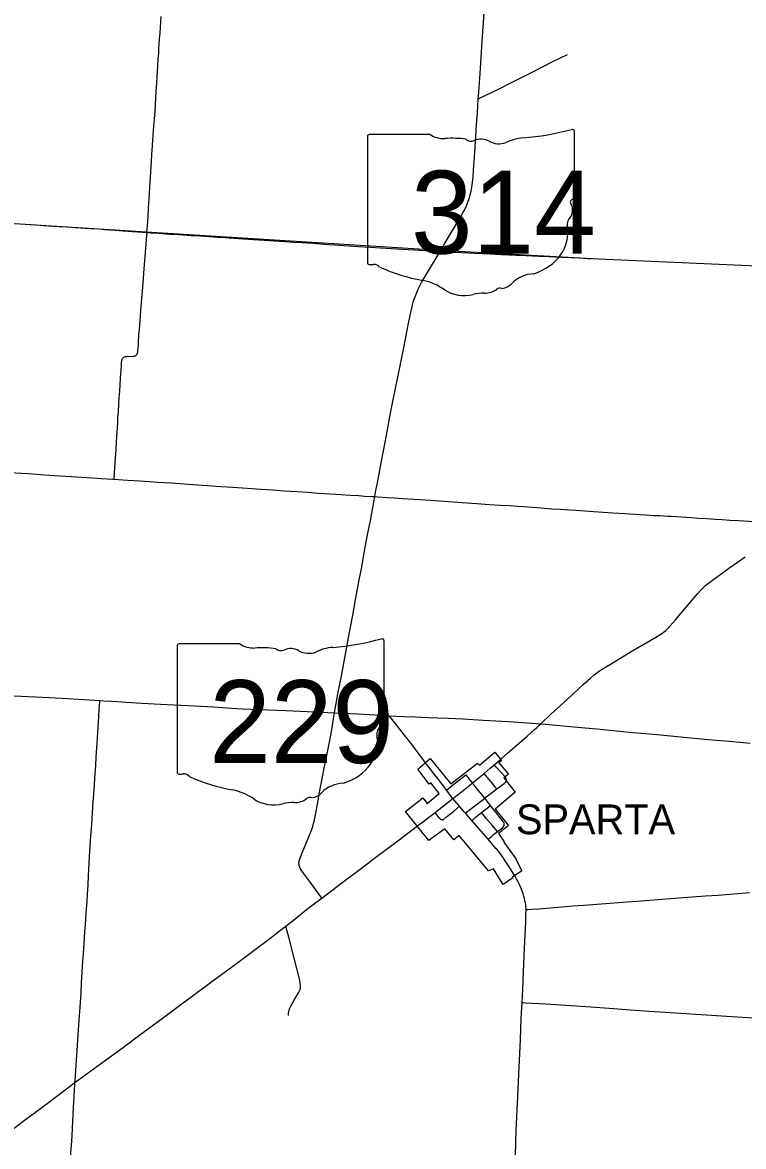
# Model space of a CAD drawing. Extents: x 1815539 to 1947826, y 273303 to 993194.
# Drawn here: x 1905397 to 1917520, y 866502 to 885394 of the extents above; entities that cross this region are included whole.
import ezdxf

# ---------------------------------------------------------------- set-up
doc = ezdxf.new("R2010")
doc.units = 0
for name, color, linetype in [('GM_X_City_Street', 7, 'Continuous'), ('GM_X_Corporation', 7, 'Continuous'), ('GM_X_Corporation_Text', 7, 'Continuous'), ('GM_X_County_Road', 7, 'Continuous'), ('GM_X_State_Route', 7, 'Continuous'), ('GM_X_Township', 7, 'Continuous'), ('GM_X_Township_Road', 7, 'Continuous'), ('SC_Shading3', 7, 'Continuous')]:
    doc.layers.add(name, color=color, linetype=linetype)

msp = doc.modelspace()

# ---------------------------------------------------------------- linework, layer by layer
at = {"layer": 'GM_X_City_Street'}
for points in [[(1913534, 872652), (1913534, 872655), (1913534, 872657), (1913534, 872659), (1913534, 872660), (1913534, 872662), (1913534, 872665), (1913533, 872671), (1913532, 872677), (1913530, 872681), (1913528, 872687), (1913526, 872690), (1913525, 872693), (1913522, 872699), (1913516, 872706), (1913510, 872715), (1913451, 872780), (1913356, 872886), (1913328, 872917)], [(1912525, 872493), (1912622, 872568), (1912846, 872742), (1912847, 872743), (1912848, 872744), (1912849, 872744), (1912850, 872744), (1912851, 872745), (1912852, 872745), (1912855, 872745)], [(1912960, 872610), (1912950, 872624), (1912867, 872732), (1912861, 872740), (1912861, 872741), (1912860, 872741), (1912858, 872743), (1912858, 872743), (1912857, 872744), (1912855, 872745)], [(1913168, 872356), (1913142, 872389), (1913010, 872554), (1912997, 872571), (1912988, 872581), (1912981, 872589), (1912972, 872599), (1912960, 872610)], [(1913372, 872513), (1913357, 872532), (1913276, 872632), (1913183, 872744), (1913158, 872773)], [(1913372, 872513), (1913431, 872556), (1913496, 872605), (1913513, 872620), (1913517, 872624), (1913522, 872629), (1913525, 872634), (1913529, 872641), (1913530, 872644), (1913531, 872646), (1913532, 872648), (1913533, 872651), (1913534, 872652)], [(1913168, 872356), (1913173, 872360), (1913275, 872438), (1913352, 872498), (1913372, 872513)], [(1912843, 872105), (1912864, 872121), (1913045, 872260), (1913168, 872356)], [(1913114, 872113), (1913238, 872213), (1913263, 872235)], [(1913263, 872235), (1913168, 872356)], [(1913494, 871894), (1913496, 871899), (1913497, 871905), (1913497, 871911), (1913497, 871918), (1913496, 871928), (1913494, 871935), (1913492, 871941), (1913489, 871947), (1913484, 871956), (1913474, 871969), (1913451, 872000), (1913424, 872034), (1913353, 872122), (1913328, 872155), (1913283, 872211), (1913263, 872235)], [(1912453, 871991), (1912449, 871991), (1912446, 871992), (1912443, 871993), (1912441, 871994), (1912438, 871995), (1912436, 871996), (1912434, 871997), (1912430, 872000), (1912426, 872003), (1912421, 872009), (1912417, 872012), (1912413, 872017), (1912388, 872046), (1912357, 872085), (1912333, 872117)], [(1912453, 871991), (1912456, 871991), (1912459, 871991), (1912462, 871992), (1912465, 871992), (1912466, 871992), (1912467, 871993), (1912469, 871994), (1912470, 871995), (1912471, 871996), (1912473, 871997), (1912526, 872041), (1912647, 872140), (1912742, 872221)], [(1912952, 871981), (1912972, 871998), (1913010, 872029), (1913114, 872113)], [(1913384, 871796), (1913287, 871910), (1913199, 872009), (1913160, 872057), (1913114, 872113)], [(1913384, 871796), (1913466, 871859), (1913486, 871878), (1913491, 871885), (1913492, 871889), (1913494, 871894)], [(1913225, 871666), (1913252, 871688), (1913289, 871719), (1913313, 871740), (1913340, 871762), (1913384, 871796)]]:
    msp.add_lwpolyline(points, dxfattribs=at)
at = {"layer": 'GM_X_Corporation'}
msp.add_lwpolyline([(1913233, 871137), (1912739, 871727), (1912650, 871656), (1912497, 871840), (1912228, 871646), (1911837, 872131), (1912128, 872361), (1912202, 872267), (1912400, 872433), (1912262, 872613), (1912235, 872592), (1912045, 872846), (1912253, 873024), (1912601, 872595), (1913046, 872947), (1913082, 872913), (1913338, 873127), (1913450, 872989), (1913407, 872950), (1913568, 872762), (1913491, 872701), (1913680, 872455), (1913345, 872174), (1913569, 871895), (1913400, 871760), (1913496, 871622), (1913488, 871616), (1913679, 871355), (1913791, 871135), (1913633, 871028), (1913642, 871016), (1913476, 870904), (1913318, 871168)], close=True, dxfattribs=at)
at = {"layer": 'GM_X_County_Road'}
for points in [[(1905171, 882022), (1905449, 882003), (1905629, 881991), (1905826, 881978), (1906016, 881966), (1906157, 881957), (1906291, 881947), (1906537, 881932), (1906678, 881923), (1906775, 881914), (1906954, 881901), (1907085, 881891), (1907249, 881879), (1907413, 881867), (1907489, 881862)], [(1907489, 881862), (1907560, 881857), (1907691, 881850), (1907871, 881838), (1907953, 881833), (1908231, 881815), (1908378, 881805), (1908542, 881794), (1908673, 881785), (1908804, 881777), (1908869, 881773), (1909033, 881763), (1909278, 881747), (1909458, 881736), (1909624, 881726), (1909802, 881714), (1909966, 881703), (1910097, 881694), (1910277, 881682), (1910474, 881668), (1910637, 881657), (1911047, 881631), (1911243, 881618), (1911505, 881601), (1911783, 881585), (1911980, 881574), (1912259, 881558), (1912420, 881547)], [(1914112, 873607), (1914282, 873766), (1914500, 873965), (1914632, 874088), (1914825, 874266), (1914947, 874375), (1915010, 874428), (1915061, 874468), (1915101, 874496), (1915170, 874540), (1915366, 874660), (1915633, 874821), (1916057, 875070), (1916127, 875113), (1916168, 875141), (1916207, 875171), (1916243, 875205), (1916288, 875253), (1916374, 875353), (1916619, 875640), (1916747, 875789), (1916801, 875850), (1916846, 875897), (1916882, 875930), (1916932, 875972), (1916997, 876022), (1917291, 876232), (1917545, 876411)], [(1906279, 867576), (1906289, 867687), (1906301, 867867), (1906324, 868201), (1906336, 868382), (1906351, 868620), (1906357, 868701), (1906361, 868767), (1906372, 868930), (1906382, 869077), (1906392, 869258), (1906397, 869339), (1906403, 869437), (1906409, 869536), (1906424, 869748), (1906435, 869912), (1906448, 870108), (1906452, 870174), (1906461, 870304), (1906470, 870435), (1906482, 870615), (1906491, 870746), (1906500, 870893), (1906508, 871057), (1906514, 871155), (1906524, 871368), (1906542, 871647), (1906561, 871908), (1906582, 872219), (1906606, 872579), (1906614, 872694), (1906628, 872906), (1906638, 873054), (1906653, 873283), (1906665, 873463), (1906679, 873725), (1906688, 873859), (1906695, 873970), (1906696, 873998)], [(1906139, 865355), (1906148, 865479), (1906161, 865659), (1906173, 865815), (1906185, 866019), (1906199, 866231), (1906205, 866329), (1906219, 866526), (1906230, 866675), (1906238, 866822), (1906244, 866918), (1906256, 867164), (1906266, 867327), (1906272, 867458), (1906276, 867540), (1906279, 867576)]]:
    msp.add_lwpolyline(points, dxfattribs=at)
at = {"layer": 'GM_X_State_Route'}
for points in [[(1910643, 873793), (1910707, 874140), (1910753, 874381), (1910856, 874930), (1910907, 875204), (1910949, 875430), (1910998, 875688), (1911060, 876027), (1911100, 876237), (1911144, 876479), (1911200, 876785), (1911246, 877026), (1911292, 877268), (1911321, 877425), (1911339, 877526), (1911369, 877687), (1911428, 877994), (1911506, 878396), (1911563, 878703), (1911604, 878919), (1911626, 879026), (1911752, 879649), (1911812, 879955), (1911861, 880196), (1911884, 880313), (1911926, 880517), (1911942, 880591), (1911954, 880646), (1911968, 880694), (1911983, 880745), (1911997, 880785), (1912014, 880829), (1912031, 880868), (1912045, 880898), (1912074, 880959), (1912108, 881023), (1912207, 881194), (1912420, 881547), (1912494, 881672), (1912578, 881813), (1912645, 881926), (1912755, 882109), (1912803, 882194), (1912833, 882252), (1912861, 882312), (1912886, 882372), (1912907, 882434), (1912926, 882496), (1912940, 882560), (1912952, 882624), (1912963, 882705), (1912973, 882803), (1912982, 882918), (1912995, 883130), (1913018, 883474), (1913026, 883589), (1913037, 883752), (1913045, 883867), (1913053, 883997), (1913061, 884110), (1913069, 884225), (1913090, 884536), (1913107, 884798), (1913128, 885093), (1913147, 885387), (1913176, 885829)], [(1905259, 874074), (1905735, 874054), (1906062, 874039), (1906439, 874017), (1906696, 873998), (1906766, 873993), (1906995, 873980), (1907143, 873972), (1907404, 873956), (1907716, 873938), (1907945, 873925), (1908289, 873909), (1908616, 873889), (1908911, 873869), (1909091, 873858), (1909238, 873850), (1909533, 873839), (1909828, 873828), (1910419, 873804), (1910643, 873793)], [(1910643, 873793), (1911029, 873772), (1911523, 873744), (1911561, 873742)], [(1911561, 873742), (1911801, 873729), (1911998, 873721), (1912211, 873713), (1912555, 873700), (1912799, 873688), (1913141, 873670), (1913566, 873644), (1913959, 873618), (1914112, 873607)], [(1912172, 872953), (1912128, 873011), (1911930, 873273), (1911800, 873443), (1911660, 873625), (1911597, 873701), (1911561, 873742)], [(1913438, 873010), (1913558, 873116), (1913668, 873215), (1913880, 873400), (1913999, 873504), (1914042, 873542), (1914078, 873576), (1914112, 873607)], [(1914112, 873607), (1914188, 873602), (1914727, 873549), (1915054, 873520), (1915657, 873463), (1916065, 873425), (1916572, 873378), (1916930, 873345), (1917338, 873308), (1917632, 873282)], [(1913394, 872974), (1913438, 873010)], [(1912037, 871890), (1912059, 871906), (1912333, 872117), (1912369, 872145), (1912634, 872350), (1912779, 872464), (1912920, 872577), (1912960, 872610), (1913048, 872680), (1913158, 872773), (1913262, 872859), (1913328, 872917), (1913394, 872974)], [(1913370, 871497), (1913357, 871513), (1913225, 871666), (1912984, 871944), (1912952, 871981), (1912843, 872105), (1912823, 872127), (1912742, 872221), (1912634, 872350), (1912525, 872493), (1912491, 872539), (1912254, 872850), (1912172, 872953)], [(1905195, 866767), (1905433, 866942), (1905656, 867109), (1905788, 867207), (1906115, 867454), (1906279, 867576), (1906339, 867621), (1906525, 867756), (1906671, 867862), (1907094, 868173), (1907371, 868378), (1907767, 868670), (1907925, 868788), (1908084, 868904), (1908229, 869012), (1908560, 869258), (1908996, 869580), (1909598, 870031), (1909740, 870142), (1909822, 870205), (1909980, 870331), (1910174, 870483), (1910330, 870603), (1910428, 870676), (1910790, 870948), (1911118, 871196), (1911340, 871366), (1911708, 871642), (1912037, 871890)], [(1913672, 871054), (1913601, 871170), (1913513, 871303), (1913471, 871366), (1913415, 871442), (1913370, 871497)], [(1913685, 866348), (1913693, 866577), (1913699, 866773), (1913710, 867002), (1913725, 867346), (1913749, 867838), (1913769, 868296), (1913784, 868657), (1913796, 868921), (1913807, 869148), (1913827, 869574), (1913837, 869836), (1913858, 870277), (1913862, 870354), (1913862, 870407), (1913864, 870466), (1913864, 870483), (1913864, 870489), (1913863, 870507), (1913861, 870532), (1913857, 870560), (1913852, 870595), (1913845, 870631), (1913837, 870668), (1913828, 870704), (1913814, 870751), (1913788, 870829), (1913772, 870867), (1913755, 870904), (1913731, 870951), (1913710, 870992), (1913672, 871054)]]:
    msp.add_lwpolyline(points, dxfattribs=at)
at = {"layer": 'GM_X_Township'}
msp.add_lwpolyline([(1929313, 880637), (1926519, 880798), (1923978, 880945), (1923826, 880954), (1918127, 881283), (1915079, 881414), (1912418, 881561), (1907482, 881867), (1902065, 882212), (1902276, 885593), (1902366, 887154), (1902378, 887248), (1902624, 890798), (1902935, 895772), (1903241, 901246), (1903453, 905734), (1903500, 906547), (1903661, 909327)], dxfattribs=at)
at = {"layer": 'GM_X_Township_Road'}
for points in [[(1907489, 881862), (1907499, 881979), (1907508, 882126), (1907517, 882274), (1907533, 882519), (1907545, 882716), (1907554, 882880), (1907560, 882978), (1907564, 883060), (1907572, 883174), (1907577, 883245), (1907583, 883325), (1907590, 883423), (1907607, 883658), (1907616, 883766), (1907627, 883908), (1907641, 884120), (1907647, 884235), (1907657, 884382), (1907663, 884480), (1907673, 884660), (1907681, 884775), (1907687, 884873), (1907692, 884955), (1907703, 885118), (1907711, 885216), (1907718, 885314), (1907730, 885495)], [(1913061, 884110), (1913174, 884164), (1913389, 884270), (1913653, 884402), (1913800, 884476), (1913975, 884566), (1914151, 884656), (1914312, 884738), (1914444, 884801), (1914559, 884855)], [(1906935, 877716), (1906936, 877737), (1906944, 877818), (1906952, 877917), (1906962, 878064), (1906971, 878212), (1906979, 878343), (1906985, 878424), (1906998, 878670), (1907003, 878752), (1907010, 878850), (1907018, 878981), (1907025, 879096), (1907028, 879128), (1907033, 879210), (1907038, 879292), (1907047, 879428), (1907054, 879547), (1907060, 879632), (1907063, 879681), (1907067, 879713), (1907071, 879729), (1907078, 879744), (1907088, 879756), (1907100, 879766), (1907115, 879774), (1907131, 879778), (1907147, 879781), (1907164, 879783), (1907246, 879782), (1907263, 879783), (1907279, 879785), (1907293, 879791), (1907307, 879800), (1907319, 879812), (1907328, 879827), (1907337, 879854), (1907339, 879873), (1907343, 879929), (1907346, 879988), (1907348, 880051), (1907352, 880103), (1907355, 880132), (1907356, 880160), (1907362, 880225), (1907371, 880324), (1907374, 880373), (1907388, 880552), (1907389, 880569), (1907393, 880618), (1907411, 880814), (1907426, 881011), (1907445, 881256), (1907456, 881386), (1907477, 881665), (1907487, 881812), (1907488, 881845), (1907489, 881862)], [(1912420, 881547), (1912541, 881539), (1912639, 881533), (1912787, 881527), (1912983, 881518), (1913131, 881511), (1913262, 881505), (1913442, 881496), (1913704, 881485), (1913868, 881477), (1914081, 881468), (1914245, 881462), (1914458, 881452), (1914625, 881444), (1914753, 881438), (1914901, 881429), (1914963, 881427)], [(1904181, 877893), (1904201, 877892), (1904299, 877888), (1904430, 877881), (1904512, 877877), (1904659, 877867), (1904790, 877859), (1905003, 877844), (1905183, 877832), (1905379, 877820), (1905494, 877813), (1905854, 877787), (1906214, 877763), (1906574, 877738), (1906721, 877728), (1906918, 877717), (1906935, 877716)], [(1906935, 877716), (1907164, 877701), (1907376, 877688), (1907671, 877669), (1907900, 877654), (1908195, 877633), (1908342, 877624)], [(1908342, 877624), (1908506, 877614), (1908735, 877597), (1908931, 877584), (1909095, 877572), (1909259, 877562), (1909324, 877557), (1909504, 877543), (1909602, 877536), (1909798, 877523), (1910011, 877508), (1910190, 877497), (1910369, 877485), (1910755, 877460), (1910905, 877450), (1911049, 877442), (1911147, 877435), (1911290, 877427), (1911321, 877425)], [(1911321, 877425), (1911378, 877422), (1911527, 877410), (1911644, 877404), (1911780, 877395), (1912174, 877368), (1912559, 877340), (1912722, 877329), (1912792, 877324), (1913038, 877308), (1913175, 877299), (1913340, 877289), (1913433, 877283), (1913577, 877273), (1913725, 877263), (1913826, 877256), (1913977, 877245), (1914120, 877235), (1914292, 877222), (1914443, 877212), (1914508, 877208), (1914590, 877203), (1914705, 877195), (1914852, 877185), (1914999, 877175), (1915081, 877169), (1915162, 877165), (1915326, 877154), (1915522, 877142), (1915604, 877137), (1915702, 877132), (1915784, 877127), (1915882, 877119), (1916013, 877110), (1916112, 877105), (1916243, 877098), (1916308, 877094), (1916390, 877090), (1916553, 877080), (1916651, 877073), (1916766, 877065), (1916897, 877057), (1917044, 877048), (1917158, 877040), (1917289, 877030), (1917437, 877022), (1917699, 877009)], [(1910428, 870676), (1910417, 870691), (1910238, 870939), (1910121, 871096), (1910084, 871150), (1910067, 871178), (1910060, 871192), (1910054, 871207), (1910050, 871222), (1910047, 871237), (1910046, 871253), (1910046, 871269), (1910048, 871285), (1910051, 871301), (1910059, 871333), (1910069, 871364), (1910097, 871440), (1910142, 871546), (1910206, 871697), (1910256, 871819), (1910278, 871881), (1910292, 871929), (1910307, 871993), (1910330, 872106), (1910367, 872317), (1910387, 872430), (1910425, 872623), (1910466, 872833), (1910513, 873073), (1910535, 873188), (1910557, 873300), (1910590, 873478), (1910625, 873688), (1910643, 873793)], [(1913864, 870483), (1913901, 870486), (1913966, 870490), (1914081, 870499), (1914457, 870529), (1914654, 870545), (1914916, 870565), (1915129, 870583), (1915276, 870594), (1915555, 870616), (1915735, 870628), (1916144, 870660), (1916505, 870686), (1916882, 870713), (1917095, 870729), (1917357, 870750), (1917619, 870770)], [(1909868, 868703), (1909869, 868736), (1909873, 868768), (1909887, 868815), (1909915, 868874), (1909972, 868973), (1910038, 869087), (1910059, 869131), (1910063, 869140), (1910066, 869146), (1910067, 869152), (1910069, 869159), (1910070, 869164), (1910071, 869172), (1910072, 869181), (1910072, 869188), (1910071, 869194), (1910070, 869203), (1910069, 869215), (1910066, 869234), (1910063, 869255), (1910058, 869286), (1910047, 869341), (1909959, 869690), (1909885, 869976), (1909822, 870205)], [(1913796, 868921), (1913819, 868920), (1913856, 868918), (1914196, 868898), (1914441, 868881), (1914711, 868865), (1914950, 868848), (1915263, 868826), (1915622, 868800), (1915933, 868778), (1916555, 868736), (1916718, 868726), (1917848, 868654)]]:
    msp.add_lwpolyline(points, dxfattribs=at)
at = {"layer": 'SC_Shading3'}
for p, q in [((1911195, 883474), (1911195, 881360)), ((1912249, 883510), (1911230, 883510)), ((1914676, 882457), (1914676, 883562)), ((1914676, 882457), (1914676, 882457)), ((1907997, 874911), (1907997, 872798)), ((1909050, 874948), (1908031, 874948)), ((1911477, 873895), (1911477, 875000)), ((1911477, 873895), (1911477, 873895))]:
    msp.add_line(p, q, dxfattribs=at)
for centre, major_axis, start_param, end_param in [((1913436, 886391), (3691, 0), 4.814394, 5.042369), ((1914637, 883567), (38.7, 0), 6.141152, 7.989035), ((1911235, 883478), (40.3, 0), 1.712693, 3.28349), ((1912492, 883755), (391, 0), 4.042523, 4.731795), ((1912621, 882324), (1404, 0), 1.404758, 1.657858), ((1912940, 883489), (113, 0), 3.836095, 5.185415), ((1913106, 883245), (235, 0), 0.950623, 2.079405), ((1913409, 883580), (282, 0), 4.081561, 5.145723), ((1913907, 882865), (743, 0), 1.699011, 2.107814), ((1914635, 882453), (41.5, 0), 5.05454, 6.418171), ((1914667, 882376), (60, 0), 1.883978, 3.671073), ((1914285, 882236), (360, 0), 5.934695, 6.695948), ((1914815, 881994), (262, 0), 2.387724, 3.262537), ((1913643, 881854), (923, 0), 5.101752, 6.440018), ((1911236, 881356), (40.7, 0), 3.00124, 4.508301), ((1911242, 881572), (310, 0), 4.665946, 4.897461), ((1911305, 881238), (112, 0), 0.519207, 1.627899), ((1912719, 883137), (2665, 0), 4.195997, 4.488961), ((1914032, 880767), (506, 0), 1.647645, 2.488434), ((1911924, 880411), (834, 0), 0.823519, 1.323587), ((1913425, 880865), (79.4, 0), 1.147584, 2.315152), ((1913392, 881156), (298, 0), 4.937069, 5.64225), ((1912826, 881228), (529, 0), 4.026481, 4.996735), ((1913132, 880497), (435, 0), 1.495662, 1.94098), ((1913170, 881070), (282, 0), 4.691044, 5.507374), ((1908037, 874916), (40.3, 0), 1.712693, 3.28349), ((1909293, 875193), (391, 0), 4.042523, 4.731795), ((1909423, 873761), (1404, 0), 1.404758, 1.657858), ((1909907, 874682), (235, 0), 0.950623, 2.079405), ((1910708, 874302), (743, 0), 1.699011, 2.107814), ((1910237, 877829), (3691, 0), 4.814394, 5.042369), ((1911438, 875005), (38.7, 0), 6.141152, 7.989035), ((1909741, 874927), (113, 0), 3.836095, 5.185415), ((1910210, 875017), (282, 0), 4.081561, 5.145723), ((1911468, 873813), (60, 0), 1.883978, 3.671073), ((1911087, 873674), (360, 0), 5.934695, 6.695948), ((1911436, 873890), (41.5, 0), 5.05454, 6.418171), ((1911616, 873432), (262, 0), 2.387724, 3.262537), ((1910444, 873291), (923, 0), 5.101752, 6.440018), ((1908037, 872793), (40.7, 0), 3.00124, 4.508301), ((1908043, 873010), (310, 0), 4.665946, 4.897461), ((1908107, 872676), (112, 0), 0.519207, 1.627899), ((1909520, 874575), (2665, 0), 4.195997, 4.488961), ((1908725, 871849), (834, 0), 0.823519, 1.323587), ((1910193, 872593), (298, 0), 4.937069, 5.64225), ((1910833, 872205), (506, 0), 1.647645, 2.488434), ((1909627, 872666), (529, 0), 4.026481, 4.996735), ((1909933, 871935), (435, 0), 1.495662, 1.94098), ((1909972, 872507), (282, 0), 4.691044, 5.507374), ((1910227, 872303), (79.4, 0), 1.147584, 2.315152)]:
    msp.add_ellipse(centre, major_axis=major_axis, ratio=0.8, start_param=start_param, end_param=end_param, dxfattribs=at)

# ---------------------------------------------------------------- texts
at = {"layer": 'GM_X_Corporation_Text'}
msp.add_text('SPARTA', height=500, rotation=0, dxfattribs=at).set_placement((1913694, 871751))
at = {"layer": 'SC_Shading3'}
for s, p in [('314', (1911929, 881509)), ('229', (1908537, 872947))]:
    msp.add_text(s, height=1392.2, dxfattribs=at).set_placement(p)

doc.saveas('drawing.dxf')
